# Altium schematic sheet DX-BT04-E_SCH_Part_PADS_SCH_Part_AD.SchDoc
size A4
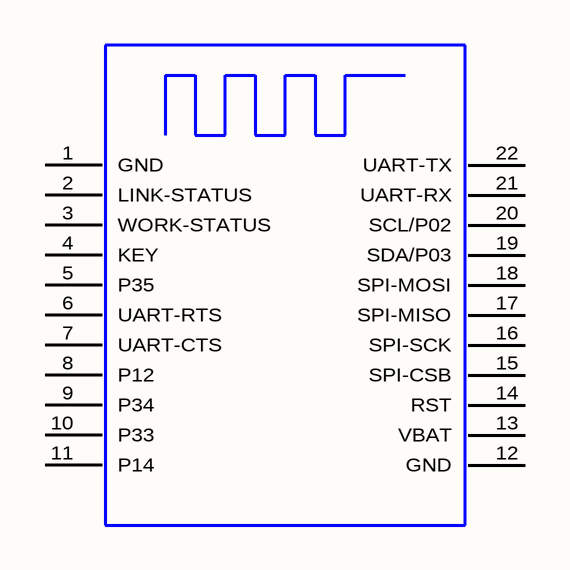
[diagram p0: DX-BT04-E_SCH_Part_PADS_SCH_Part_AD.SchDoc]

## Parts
U?  DX-BT04-E  [DX-BT04-E]  (value not drawn)

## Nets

Not connected (* = marked no-connect by the designer): U? 1(GND) 2(LINK-STATUS) 3(WORK-STATUS) 4(KEY) 5(P35) 6(UART-RTS) 7(UART-CTS) 8(P12) 9(P34) 10(P33) 11(P14) 12(GND) 13(VBAT) 14(RST) 15(SPI-CSB) 16(SPI-SCK) 17(SPI-MISO) 18(SPI-MOSI) 19(SDA/P03) 20(SCL/P02) 21(UART-RX) 22(UART-TX)

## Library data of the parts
U? = DX-BT04-E: PCB DECAL: DX-BT24-S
